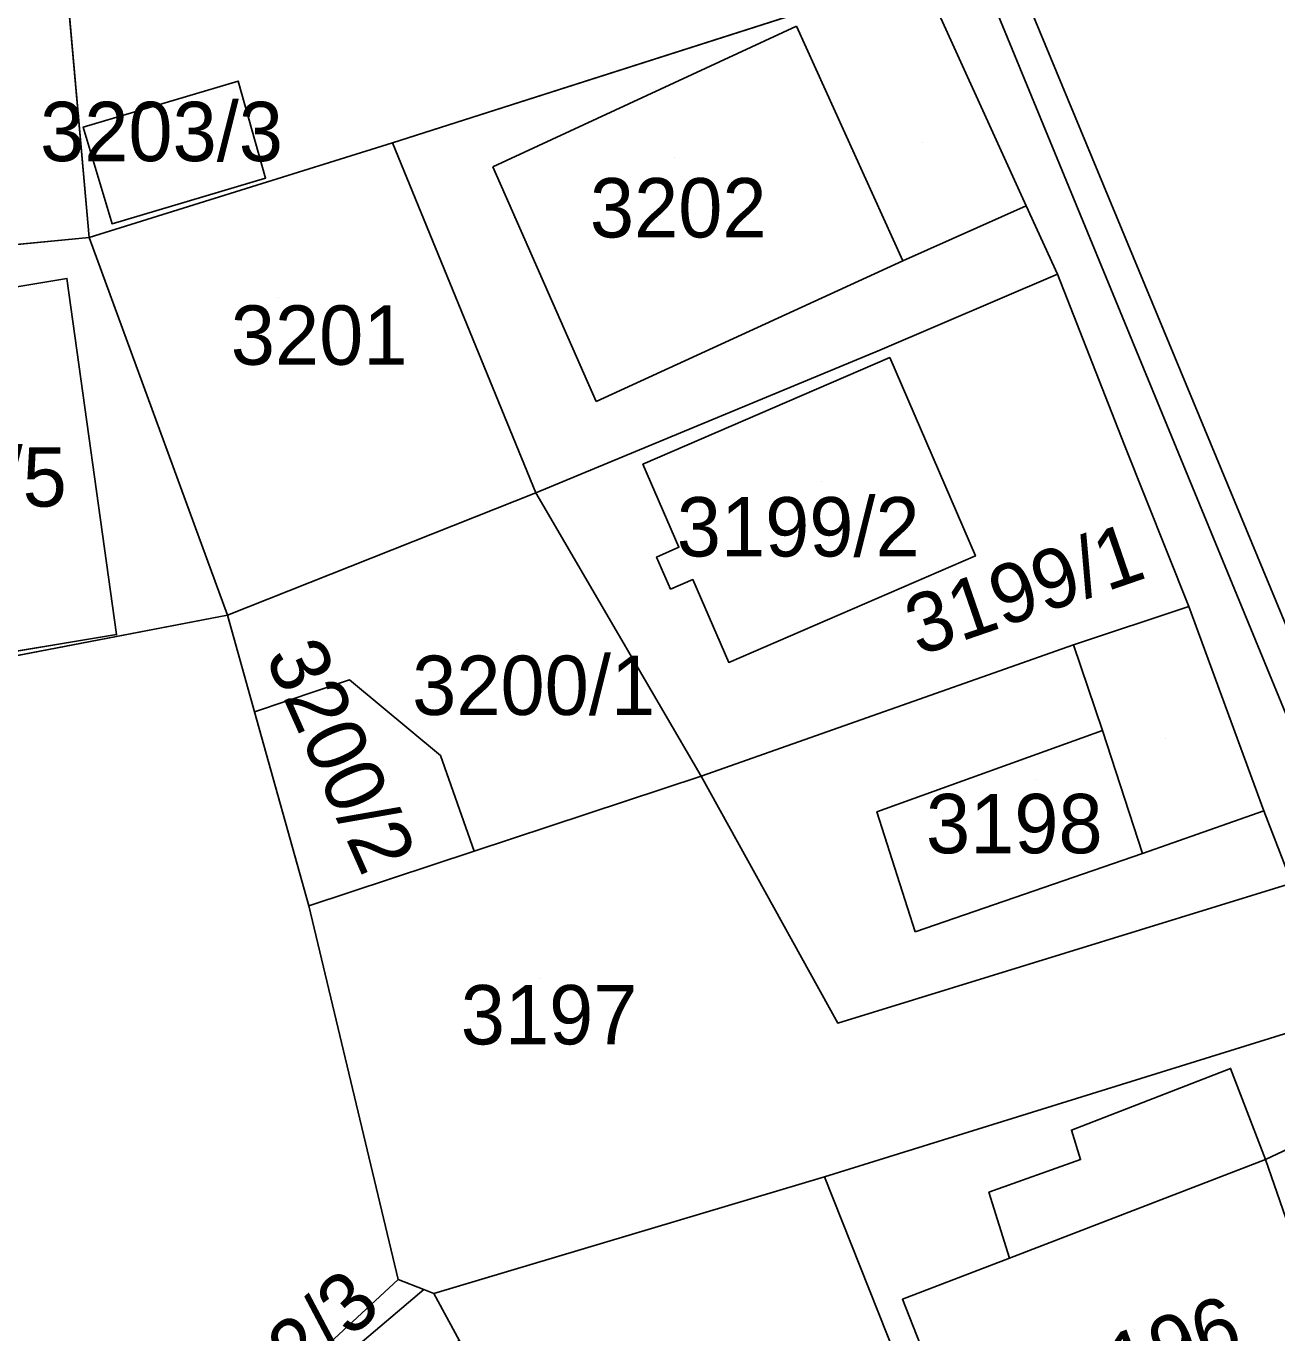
# Model space of a CAD drawing. Extents: x -262657 to -261595, y -1238015 to -1237156.
# Drawn here: x -261921.51 to -261879.39, y -1237897.37 to -1237853.34 of the extents above; entities that cross this region are included whole.
import ezdxf

# ---------------------------------------------------------------- set-up
doc = ezdxf.new("R2010")
doc.units = 0
for name, color, linetype in [('body_kn', 7, 'Continuous'), ('kladpar_druhypozemkov', 7, 'Continuous'), ('kladpar_hranice', 7, 'Continuous'), ('kladpar_parcelnecisla', 7, 'Continuous'), ('kladpar_plochy', 7, 'Continuous'), ('zappar_hrandruhpozemk', 7, 'Continuous')]:
    doc.layers.add(name, color=color, linetype=linetype)

msp = doc.modelspace()

# ---------------------------------------------------------------- linework, layer by layer
at = {"layer": 'body_kn'}
for p, q in [((-261914.37, -1237855.19), (-261914.37, -1237855.19)), ((-261919.59, -1237856.74), (-261919.59, -1237856.74)), ((-261919.59, -1237856.74), (-261919.59, -1237856.74)), ((-261909.18, -1237857.27), (-261909.18, -1237857.27)), ((-261905.8, -1237858.08), (-261905.8, -1237858.08)), ((-261905.8, -1237858.08), (-261905.8, -1237858.08)), ((-261913.45, -1237858.46), (-261913.45, -1237858.46)), ((-261887.83, -1237859.39), (-261887.83, -1237859.39)), ((-261918.62, -1237860), (-261918.62, -1237860)), ((-261919.39, -1237860.46), (-261919.39, -1237860.46)), ((-261919.39, -1237860.46), (-261919.39, -1237860.46)), ((-261891.99, -1237861.25), (-261891.99, -1237861.25)), ((-261891.99, -1237861.25), (-261891.99, -1237861.25)), ((-261920.14, -1237861.84), (-261920.14, -1237861.84)), ((-261886.78, -1237861.7), (-261886.78, -1237861.7)), ((-261886.78, -1237861.7), (-261886.78, -1237861.7)), ((-261892.76, -1237864.26), (-261892.76, -1237864.26)), ((-261892.43, -1237864.51), (-261892.43, -1237864.51)), ((-261902.32, -1237865.99), (-261902.32, -1237865.99)), ((-261884.52, -1237867.46), (-261884.52, -1237867.46)), ((-261900.74, -1237868.1), (-261900.74, -1237868.1)), ((-261900.74, -1237868.1), (-261900.74, -1237868.1)), ((-261904.35, -1237869.07), (-261904.35, -1237869.07)), ((-261904.35, -1237869.07), (-261904.35, -1237869.07)), ((-261900.28, -1237871.23), (-261900.28, -1237871.23)), ((-261899.53, -1237870.9), (-261899.53, -1237870.9)), ((-261889.54, -1237871.19), (-261889.54, -1237871.19)), ((-261899.06, -1237871.99), (-261899.06, -1237871.99)), ((-261899.81, -1237872.31), (-261899.81, -1237872.31)), ((-261882.36, -1237872.9), (-261882.36, -1237872.9)), ((-261882.36, -1237872.9), (-261882.36, -1237872.9)), ((-261914.73, -1237873.19), (-261914.73, -1237873.19)), ((-261918.47, -1237873.84), (-261918.47, -1237873.84)), ((-261886.24, -1237874.19), (-261886.24, -1237874.19)), ((-261886.24, -1237874.19), (-261886.24, -1237874.19)), ((-261897.85, -1237874.78), (-261897.85, -1237874.78)), ((-261910.62, -1237875.37), (-261910.62, -1237875.37)), ((-261910.62, -1237875.37), (-261910.62, -1237875.37)), ((-261913.82, -1237876.45), (-261913.82, -1237876.45)), ((-261885.26, -1237877.07), (-261885.26, -1237877.07)), ((-261885.26, -1237877.07), (-261885.26, -1237877.07)), ((-261907.56, -1237877.92), (-261907.56, -1237877.92)), ((-261898.78, -1237878.61), (-261898.78, -1237878.61)), ((-261898.78, -1237878.61), (-261898.78, -1237878.61)), ((-261892.86, -1237879.81), (-261892.86, -1237879.81)), ((-261879.83, -1237879.78), (-261879.83, -1237879.78)), ((-261906.43, -1237881.14), (-261906.43, -1237881.14)), ((-261883.92, -1237881.22), (-261883.92, -1237881.22)), ((-261883.92, -1237881.22), (-261883.92, -1237881.22)), ((-261911.99, -1237882.98), (-261911.99, -1237882.98)), ((-261911.99, -1237882.98), (-261911.99, -1237882.98)), ((-261891.57, -1237883.86), (-261891.57, -1237883.86)), ((-261894.18, -1237886.93), (-261894.18, -1237886.93)), ((-261880.95, -1237888.46), (-261880.95, -1237888.46)), ((-261886.31, -1237890.54), (-261886.31, -1237890.54)), ((-261886, -1237891.53), (-261886, -1237891.53)), ((-261879.77, -1237891.53), (-261879.77, -1237891.53)), ((-261894.62, -1237892.11), (-261894.62, -1237892.11)), ((-261889.09, -1237892.63), (-261889.09, -1237892.63)), ((-261888.4, -1237894.85), (-261888.4, -1237894.85)), ((-261888.4, -1237894.85), (-261888.4, -1237894.85)), ((-261908.99, -1237895.57), (-261908.99, -1237895.57)), ((-261908.12, -1237895.91), (-261908.12, -1237895.91)), ((-261907.78, -1237896.04), (-261907.78, -1237896.04)), ((-261892, -1237896.24), (-261892, -1237896.24))]:
    msp.add_line(p, q, dxfattribs=at)
at = {"layer": 'kladpar_druhypozemkov'}
for p, q in [((-261916.41, -1237856.32), (-261916.41, -1237856.32)), ((-261891.32, -1237857.26), (-261891.32, -1237857.26)), ((-261899.69, -1237857.75), (-261899.69, -1237857.75)), ((-261913.03, -1237862.47), (-261913.03, -1237862.47)), ((-261894.72, -1237868.67), (-261894.72, -1237868.67)), ((-261887.2, -1237870.9), (-261887.2, -1237870.9)), ((-261904.95, -1237874.36), (-261904.95, -1237874.36)), ((-261883.15, -1237877.34), (-261883.15, -1237877.34)), ((-261909.28, -1237878.62), (-261909.28, -1237878.62)), ((-261887.48, -1237878.72), (-261887.48, -1237878.72)), ((-261904.19, -1237885.42), (-261904.19, -1237885.42)), ((-261909.5, -1237896.39), (-261909.5, -1237896.39)), ((-261884.18, -1237897.24), (-261884.18, -1237897.24))]:
    msp.add_line(p, q, dxfattribs=at)
at = {"layer": 'kladpar_hranice'}
msp.add_line((-261943.52, -1237862.78), (-261919.39, -1237860.46), dxfattribs=at)
for points in [[(-261867.89, -1237908.17), (-261869.84, -1237903.85), (-261871.28, -1237900.38), (-261871.81, -1237899.1), (-261875.73, -1237889.62), (-261876.97, -1237886.62), (-261878.89, -1237882.22), (-261879.83, -1237879.78), (-261882.36, -1237872.9), (-261884.52, -1237867.46), (-261886.78, -1237861.7), (-261887.83, -1237859.39), (-261891.38, -1237851.58), (-261896.16, -1237839.29), (-261898.28, -1237834.11), (-261898.91, -1237832.53), (-261900.73, -1237828.11), (-261906.4, -1237814.7), (-261906.69, -1237814.03), (-261914.09, -1237816.76)], [(-261922.58, -1237826.51), (-261921.51, -1237835.19), (-261920.85, -1237843.48), (-261920.52, -1237847.68), (-261920.48, -1237848.23), (-261919.39, -1237860.46), (-261943.52, -1237862.78), (-261943.56, -1237862.36), (-261945.19, -1237844.04)], [(-261896.16, -1237839.29), (-261891.38, -1237851.58), (-261909.18, -1237857.27)], [(-261909.18, -1237857.27), (-261919.39, -1237860.46), (-261920.48, -1237848.23)], [(-261891.38, -1237851.58), (-261887.83, -1237859.39), (-261886.78, -1237861.7), (-261892.76, -1237864.26), (-261904.35, -1237869.07), (-261909.18, -1237857.27), (-261891.38, -1237851.58)], [(-261913.45, -1237858.46), (-261914.37, -1237855.19), (-261919.59, -1237856.74), (-261918.62, -1237860), (-261913.45, -1237858.46)], [(-261919.59, -1237856.74), (-261914.37, -1237855.19), (-261913.45, -1237858.46), (-261918.62, -1237860), (-261919.59, -1237856.74)], [(-261904.35, -1237869.07), (-261914.73, -1237873.19), (-261919.39, -1237860.46), (-261909.18, -1237857.27), (-261904.35, -1237869.07)], [(-261919.39, -1237860.46), (-261914.73, -1237873.19), (-261948.53, -1237879.67), (-261947.91, -1237862.67), (-261943.56, -1237862.36), (-261943.52, -1237862.78)], [(-261918.47, -1237873.84), (-261920.14, -1237861.84), (-261930.25, -1237863.53), (-261928.54, -1237875.51), (-261918.47, -1237873.84)], [(-261930.25, -1237863.53), (-261920.14, -1237861.84), (-261918.47, -1237873.84), (-261928.54, -1237875.51), (-261930.25, -1237863.53)], [(-261882.36, -1237872.9), (-261886.24, -1237874.19), (-261898.78, -1237878.61), (-261904.35, -1237869.07), (-261892.76, -1237864.26), (-261886.78, -1237861.7)], [(-261886.78, -1237861.7), (-261884.52, -1237867.46), (-261882.36, -1237872.9)], [(-261889.54, -1237871.19), (-261892.43, -1237864.51), (-261900.74, -1237868.1), (-261899.53, -1237870.9), (-261900.28, -1237871.23), (-261899.81, -1237872.31), (-261899.06, -1237871.99), (-261897.85, -1237874.78), (-261889.54, -1237871.19)], [(-261900.74, -1237868.1), (-261892.43, -1237864.51), (-261889.54, -1237871.19), (-261897.85, -1237874.78), (-261899.06, -1237871.99), (-261899.81, -1237872.31), (-261900.28, -1237871.23), (-261899.53, -1237870.9), (-261900.74, -1237868.1)], [(-261904.35, -1237869.07), (-261898.78, -1237878.61), (-261906.43, -1237881.14), (-261907.56, -1237877.92), (-261910.62, -1237875.37), (-261913.82, -1237876.45), (-261914.73, -1237873.19), (-261904.35, -1237869.07)], [(-261882.36, -1237872.9), (-261879.83, -1237879.78), (-261878.89, -1237882.22), (-261894.18, -1237886.93), (-261898.78, -1237878.61), (-261886.24, -1237874.19), (-261882.36, -1237872.9)], [(-261911.99, -1237882.98), (-261908.99, -1237895.57), (-261917.74, -1237903.69), (-261921.19, -1237906.89), (-261923.29, -1237901.37), (-261923.57, -1237900.64), (-261946.7, -1237908.19), (-261946.51, -1237902.1), (-261947.07, -1237897.23), (-261949.09, -1237879.78), (-261948.53, -1237879.67), (-261914.73, -1237873.19), (-261913.82, -1237876.45), (-261911.99, -1237882.98)], [(-261910.62, -1237875.37), (-261907.56, -1237877.92), (-261906.43, -1237881.14), (-261911.99, -1237882.98), (-261913.82, -1237876.45), (-261910.62, -1237875.37)], [(-261898.78, -1237878.61), (-261894.18, -1237886.93), (-261878.89, -1237882.22), (-261876.97, -1237886.62), (-261894.62, -1237892.11), (-261907.78, -1237896.04), (-261908.12, -1237895.91), (-261908.99, -1237895.57), (-261911.99, -1237882.98), (-261906.43, -1237881.14), (-261898.78, -1237878.61)], [(-261876.97, -1237886.62), (-261875.73, -1237889.62), (-261871.81, -1237899.1), (-261871.28, -1237900.38), (-261888.58, -1237907.33), (-261894.62, -1237892.11), (-261876.97, -1237886.62)], [(-261871.28, -1237900.38), (-261869.84, -1237903.85), (-261871.84, -1237904.66), (-261897.63, -1237915.04), (-261906.92, -1237897.64), (-261907.78, -1237896.04), (-261894.62, -1237892.11), (-261888.58, -1237907.33), (-261871.28, -1237900.38)], [(-261897.63, -1237915.04), (-261900.02, -1237916.78), (-261908.2, -1237920.06), (-261906.56, -1237923.96), (-261905.6, -1237926.38), (-261906.65, -1237926.75), (-261910.79, -1237927.96), (-261917.58, -1237915.95), (-261921.19, -1237906.89), (-261917.74, -1237903.69), (-261912.49, -1237899.62), (-261908.12, -1237895.91), (-261907.78, -1237896.04), (-261906.92, -1237897.64)], [(-261917.74, -1237903.69), (-261908.99, -1237895.57), (-261908.12, -1237895.91), (-261912.49, -1237899.62), (-261917.74, -1237903.69)]]:
    msp.add_lwpolyline(points, dxfattribs=at)
at = {"layer": 'kladpar_plochy'}
for p, q in [((-261919.39, -1237860.46), (-261920.48, -1237848.23)), ((-261891.38, -1237851.58), (-261909.18, -1237857.27)), ((-261914.37, -1237855.19), (-261919.59, -1237856.74)), ((-261913.45, -1237858.46), (-261914.37, -1237855.19)), ((-261919.59, -1237856.74), (-261918.62, -1237860)), ((-261909.18, -1237857.27), (-261919.39, -1237860.46)), ((-261918.62, -1237860), (-261913.45, -1237858.46)), ((-261943.52, -1237862.78), (-261919.39, -1237860.46)), ((-261919.39, -1237860.46), (-261914.73, -1237873.19)), ((-261920.14, -1237861.84), (-261930.25, -1237863.53)), ((-261918.47, -1237873.84), (-261920.14, -1237861.84)), ((-261892.76, -1237864.26), (-261886.78, -1237861.7)), ((-261886.78, -1237861.7), (-261884.52, -1237867.46)), ((-261904.35, -1237869.07), (-261892.76, -1237864.26)), ((-261892.43, -1237864.51), (-261900.74, -1237868.1)), ((-261889.54, -1237871.19), (-261892.43, -1237864.51)), ((-261884.52, -1237867.46), (-261882.36, -1237872.9)), ((-261900.74, -1237868.1), (-261899.53, -1237870.9)), ((-261898.78, -1237878.61), (-261904.35, -1237869.07)), ((-261899.53, -1237870.9), (-261900.28, -1237871.23)), ((-261900.28, -1237871.23), (-261899.81, -1237872.31)), ((-261897.85, -1237874.78), (-261889.54, -1237871.19)), ((-261899.81, -1237872.31), (-261899.06, -1237871.99)), ((-261899.06, -1237871.99), (-261897.85, -1237874.78)), ((-261882.36, -1237872.9), (-261886.24, -1237874.19)), ((-261914.73, -1237873.19), (-261948.53, -1237879.67)), ((-261928.54, -1237875.51), (-261918.47, -1237873.84)), ((-261886.24, -1237874.19), (-261898.78, -1237878.61))]:
    msp.add_line(p, q, dxfattribs=at)
msp.add_lwpolyline([(-261871.81, -1237899.1), (-261875.73, -1237889.62), (-261876.97, -1237886.62), (-261878.89, -1237882.22), (-261879.83, -1237879.78), (-261882.36, -1237872.9), (-261884.52, -1237867.46), (-261886.78, -1237861.7), (-261887.83, -1237859.39), (-261891.38, -1237851.58), (-261896.16, -1237839.29), (-261898.28, -1237834.11), (-261898.91, -1237832.53), (-261900.73, -1237828.11), (-261906.4, -1237814.7), (-261906.69, -1237814.03), (-261914.09, -1237816.76), (-261923.62, -1237819.21), (-261923.89, -1237818.34), (-261924, -1237817.96), (-261923.67, -1237817.87), (-261913.97, -1237813.57)], dxfattribs=at)
for points in [[(-261945.19, -1237844.04), (-261926.38, -1237842.67), (-261926.52, -1237835.51), (-261930.89, -1237835.7), (-261931.15, -1237832.29), (-261942.76, -1237833.21), (-261946.3, -1237833.58), (-261946.74, -1237828.94), (-261922.58, -1237826.51), (-261921.51, -1237835.19), (-261920.85, -1237843.48), (-261920.52, -1237847.68), (-261920.48, -1237848.23), (-261919.39, -1237860.46), (-261943.52, -1237862.78), (-261943.56, -1237862.36)], [(-261891.38, -1237851.58), (-261887.83, -1237859.39), (-261886.78, -1237861.7), (-261892.76, -1237864.26), (-261904.35, -1237869.07), (-261909.18, -1237857.27)], [(-261919.59, -1237856.74), (-261914.37, -1237855.19), (-261913.45, -1237858.46), (-261918.62, -1237860)], [(-261904.35, -1237869.07), (-261914.73, -1237873.19), (-261919.39, -1237860.46), (-261909.18, -1237857.27)], [(-261930.25, -1237863.53), (-261920.14, -1237861.84), (-261918.47, -1237873.84), (-261928.54, -1237875.51)], [(-261900.74, -1237868.1), (-261892.43, -1237864.51), (-261889.54, -1237871.19), (-261897.85, -1237874.78), (-261899.06, -1237871.99), (-261899.81, -1237872.31), (-261900.28, -1237871.23), (-261899.53, -1237870.9)], [(-261904.35, -1237869.07), (-261898.78, -1237878.61), (-261906.43, -1237881.14), (-261907.56, -1237877.92), (-261910.62, -1237875.37), (-261913.82, -1237876.45), (-261914.73, -1237873.19)], [(-261882.36, -1237872.9), (-261879.83, -1237879.78), (-261878.89, -1237882.22), (-261894.18, -1237886.93), (-261898.78, -1237878.61), (-261886.24, -1237874.19)], [(-261911.99, -1237882.98), (-261908.99, -1237895.57), (-261917.74, -1237903.69), (-261921.19, -1237906.89), (-261923.29, -1237901.37), (-261923.57, -1237900.64), (-261946.7, -1237908.19), (-261946.51, -1237902.1), (-261947.07, -1237897.23), (-261949.09, -1237879.78), (-261948.53, -1237879.67), (-261914.73, -1237873.19), (-261913.82, -1237876.45)], [(-261910.62, -1237875.37), (-261907.56, -1237877.92), (-261906.43, -1237881.14), (-261911.99, -1237882.98), (-261913.82, -1237876.45)], [(-261898.78, -1237878.61), (-261894.18, -1237886.93), (-261878.89, -1237882.22), (-261876.97, -1237886.62), (-261894.62, -1237892.11), (-261907.78, -1237896.04), (-261908.12, -1237895.91), (-261908.99, -1237895.57), (-261911.99, -1237882.98), (-261906.43, -1237881.14)], [(-261876.97, -1237886.62), (-261875.73, -1237889.62), (-261871.81, -1237899.1), (-261871.28, -1237900.38), (-261888.58, -1237907.33), (-261894.62, -1237892.11)], [(-261871.28, -1237900.38), (-261869.84, -1237903.85), (-261871.84, -1237904.66), (-261897.63, -1237915.04), (-261906.92, -1237897.64), (-261907.78, -1237896.04), (-261894.62, -1237892.11), (-261888.58, -1237907.33)], [(-261897.63, -1237915.04), (-261900.02, -1237916.78), (-261908.2, -1237920.06), (-261906.56, -1237923.96), (-261905.6, -1237926.38), (-261906.65, -1237926.75), (-261910.79, -1237927.96), (-261917.58, -1237915.95), (-261921.19, -1237906.89), (-261917.74, -1237903.69), (-261912.49, -1237899.62), (-261908.12, -1237895.91), (-261907.78, -1237896.04), (-261906.92, -1237897.64), (-261910.24, -1237898.78), (-261905.23, -1237905.85), (-261901.28, -1237915.55)], [(-261917.74, -1237903.69), (-261908.99, -1237895.57), (-261908.12, -1237895.91), (-261912.49, -1237899.62)]]:
    msp.add_lwpolyline(points, close=True, dxfattribs=at)
at = {"layer": 'zappar_hrandruhpozemk'}
for p, q in [((-261905.8, -1237858.08), (-261895.57, -1237853.34)), ((-261902.32, -1237865.99), (-261905.8, -1237858.08)), ((-261891.99, -1237861.25), (-261887.83, -1237859.39)), ((-261886.24, -1237874.19), (-261885.26, -1237877.07)), ((-261883.92, -1237881.22), (-261879.83, -1237879.78)), ((-261879.77, -1237891.53), (-261875.73, -1237889.62)), ((-261888.4, -1237894.85), (-261879.77, -1237891.53))]:
    msp.add_line(p, q, dxfattribs=at)
for points in [[(-261875, -1237886.44), (-261927.55, -1237758.77), (-261932.46, -1237746.83)], [(-261917.3, -1237781.31), (-261875.05, -1237883.26), (-261864.96, -1237906.9)], [(-261895.57, -1237853.34), (-261891.99, -1237861.25), (-261902.32, -1237865.99)], [(-261891.57, -1237883.86), (-261892.86, -1237879.81), (-261885.26, -1237877.07)], [(-261885.26, -1237877.07), (-261883.92, -1237881.22), (-261891.57, -1237883.86)], [(-261888.19, -1237905.96), (-261888.67, -1237904.72), (-261889.55, -1237902.47), (-261892, -1237896.24), (-261888.4, -1237894.85), (-261889.09, -1237892.63), (-261886, -1237891.53), (-261886.31, -1237890.54), (-261880.95, -1237888.46), (-261879.77, -1237891.53)], [(-261879.77, -1237891.53), (-261876.47, -1237901.05), (-261885.37, -1237904.78), (-261888.19, -1237905.96)]]:
    msp.add_lwpolyline(points, dxfattribs=at)

# ---------------------------------------------------------------- texts
at = {"layer": 'kladpar_parcelnecisla'}
for s, p in [('3203/3', (-261921.045, -1237857.89)), ('3202', (-261902.527, -1237860.46)), ('3201', (-261914.621, -1237864.75)), ('3210/5', (-261928.326, -1237869.53)), ('3199/2', (-261899.6, -1237871.21)), ('3200/1', (-261908.513, -1237876.55)), ('3198', (-261891.207, -1237881.21)), ('3197', (-261906.876, -1237887.65))]:
    msp.add_text(s, height=2, dxfattribs=at).set_placement(p)
for s, rotation, p in [('3199/1', 19, (-261891.453, -1237874.571)), ('3200/2', 294, (-261913.484, -1237874.577)), ('3182/3', 42, (-261915.561, -1237902.051)), ('3196', 20, (-261886.022, -1237899.958))]:
    msp.add_text(s, height=2, rotation=rotation, dxfattribs=at).set_placement(p)

doc.saveas('drawing.dxf')
